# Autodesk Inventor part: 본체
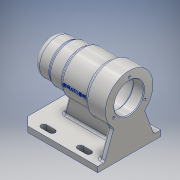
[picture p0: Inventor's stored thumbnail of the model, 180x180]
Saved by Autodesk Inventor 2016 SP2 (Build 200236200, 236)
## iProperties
Created: 2017-09
Part Number: 본체
Material: 알루미늄 6061
Document SubType Name: 모델링
Designer: Administrator
Density: 2.7 g/cm^3
Appearance: 알루미늄 - 평지
Sheet Metal Rule: 기본값_mm
Mass: 696.428 g
Surface Area: 709.296 cm^2
Volume: 257.936 cm^3
Author: Administrator
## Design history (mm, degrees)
sketch "스케치1"
  geometry: L1 (-56, -45)-(56, -45); L2 (56, -45)-(56, 45); L3 (56, 45)-(-56, 45); L4 (-56, 45)-(-56, -45); L5 (-56, -45)-(56, 45); L6 (56, -45)-(-56, 45); 1 further point
  constraints: 12 end point, 2 midpoint, 2 parallel, 1 horizontal, 1 perpendicular
  dimensions: "d0" = 112 distance of L2.end L3.end; "d1" = 90 distance of L1.end L2.end
extrude "돌출1" new body sketch "스케치1" distance "d2" = 8; taper "d3" = 0 deg
sketch "스케치4"
  geometry: L1 (56, 70)-(31, 70); L2 (31, 70)-(31, 95); L3 (31, 95)-(56, 95); L4 (56, 95)-(56, 70); L5 (31, 70)-(11, 70); L6 (11, 70)-(11, 97); L7 (11, 97)-(31, 97); L8 (31, 97)-(31, 70); L9 (11, 70)-(-28, 70); L10 (-28, 70)-(-28, 100); L11 (-28, 100)-(11, 100); L12 (11, 100)-(11, 70); L13 (-28, 70)-(-56, 70); L14 (-56, 70)-(-56, 104); L15 (-56, 104)-(-28, 104); L16 (-28, 104)-(-28, 70); L17 (-56, 0)-(-56, 8) reference; L18 (-56, 0)-(56, 0) reference; 1 further point
  constraints: 32 end point, 8 parallel, 4 horizontal, 4 perpendicular, 1 collinear
  dimensions: "d20" = 112 distance between parallel lines of L14 L4; "d21" = 25 distance of L2.end L3.end; "d22" = 45 distance between parallel lines of L6 L4; "d23" = 84 distance between parallel lines of L10 L4; "d24" = 70 distance between parallel lines of L18 L13; "d25" = 50 diameter of L3 L1; "d26" = 54 diameter of L7 L5; "d27" = 60 diameter of L11 L9; "d28" = 68 diameter of L15 L13
revolve "회전1" sketch "스케치4" stored, may be unused: angle "d29" = 90 deg
fillet "모깎기1" dims "d39" = 9
fillet "모깎기2" dims "d40" = 3
sketch "스케치7" dims "d52" = 0
  geometry: L1 (-56, 8)-(56, 8) reference; L2 (-56, 8)-(34, 8); L3 (34, 8)-(17.387, 70); L4 (17.387, 70)-(-56, 70); L5 (14, 97)-(14, 43) reference; L6 (-56, 70)-(-56, 8); L7 (-56, 0)-(56, 0) reference; L8 (56, 0)-(56, 8) reference; 1 further point
  constraints: 8 end point, 2 perpendicular, 1 point on line
  dimensions: "d41" = 70 distance between parallel lines of L7 L4; "d42" = 22 distance from line of L8 L2.end; "d43" = 105 deg angle of L1 L3
extrude "돌출5" join sketch "스케치7" stored distance "d44" = 8; taper "d45" = 0 deg
sketch "스케치8"
  geometry: L1 (-8, 90)-(-8, 0) reference; L2 (-8, 10)-(-70, 32.566); L3 (-70, 32.566)-(-70, 57.434); L4 (-70, 57.434)-(-8, 80); L5 (-8, 80)-(-8, 10); L6 (0, 0)-(-8, 0) reference; L7 (0, 90)-(-8, 90) reference; L8 (0, 90)-(0, 0) reference; 1 further point
  constraints: 8 end point, 2 point on line, 1 parallel, 1 vertical
  dimensions: "d46" = 10 distance from line of L6 L2.start; "d47" = 10 distance from line of L7 L4.end; "d48" = 110 deg angle of L1 L4; "d49" = 110 deg angle of L1 L2; "d50" = 70 distance between parallel lines of L8 L3
extrude "돌출6" join sketch "스케치8" distance "d51" = 8; taper "d52" = 0 deg
sketch "스케치9"
  geometry: L1 (-32, 34)-(-20, 34); L2 (-32, 30)-(-20, 30); L3 (-20, 38)-(-32, 38); L4 (20, 34)-(32, 34); L5 (20, 30)-(32, 30); L6 (32, 38)-(20, 38); L7 (56, -45)-(56, 45) reference; A1 r 4 centre (-32, 34) between (-32, 38) and (-32, 30); A2 r 4 centre (-20, 34) between (-20, 30) and (-20, 38); A3 r 4 centre (20, 34) between (20, 38) and (20, 30); A4 r 4 centre (32, 34) between (32, 30) and (32, 38); 3 further points
  constraints: 16 end point, 8 point on circle, 8 tangent, 4 centre point, 2 horizontal, 2 midpoint, 2 parallel, 1 horizontal alignment
  dimensions: "d53" = 34 vertical distance of point (0, 0) point (-26, 34); "d54" = 4 radius of A1; "d56" = 12 distance of L1.end L1.start; "d57" = 40 distance of L4.start L1.end; "d58" = 12 distance of L4.start L4.end; "d59" = 24 distance from line of L7 L4.end; "d60" = 4 radius of A3; "d61" = 4 radius of A2 (derived); "d62" = 4 radius of A4 (derived)
extrude "돌출7" cut sketch "스케치9" stored distance "d63" = 8; taper "d64" = 0 deg
chamfer "모따기1" distance "d65" = 12; stored, may be unused: second distance "d66" = 2, angle "d67" = 45 deg
sketch "스케치10"
  geometry: L1 (-56, 43.992)-(-56, 104) reference; L2 (-56, 70)-(-41, 70); L3 (-41, 70)-(-41, 91); L4 (-41, 91)-(-56, 91); L5 (-56, 91)-(-56, 70); L6 (-41, 70)-(13, 70); L7 (13, 70)-(13, 94); L8 (13, 94)-(-41, 94); L9 (-41, 94)-(-41, 70); L10 (13, 86.642)-(13, 70); L11 (-56, 0)-(44, 0) reference; L12 (13, 70)-(25, 70); L13 (25, 70)-(25, 91); L14 (25, 91)-(13, 91); L15 (13, 91)-(13, 70); L16 (25, 70)-(43, 70); L17 (43, 70)-(43, 87.5); L18 (43, 87.5)-(25, 87.5); L19 (25, 87.5)-(25, 70); L20 (43, 70)-(47, 70); L21 (47, 86)-(43, 86); L22 (43, 86)-(43, 70); L23 (47, 70)-(50, 70); L24 (50, 70)-(50, 80.5); L25 (50, 80.5)-(47, 80.5); L26 (47, 80.5)-(47, 70); L27 (47, 86)-(47, 70); L28 (47, 45)-(47, 95) reference; 1 further point
  constraints: 50 end point, 11 parallel, 6 horizontal, 5 perpendicular, 1 collinear, 1 point on line
  dimensions: "d68" = 70 distance between parallel lines of L11 L2; "d69" = 15 distance of L3.end L4.end; "d70" = 54 distance of L7.end L8.end; "d73" = 12 distance of L13.end L14.end; "d74" = 18 distance of L17.end L18.end; "d75" = 4 distance of L21.start L21.end; "d77" = 42 diameter of L4 L2; "d78" = 48 diameter of L8 L6; "d79" = 42 diameter of L14 L12; "d80" = 35 diameter of L18 L16; "d81" = 32 diameter of L21 L20; "d84" = 21 diameter of L25 L23; "d86" = 3 distance between parallel lines of L24 L27; "d105" = 7 distance between parallel lines of L22 L24 (derived)
revolve "회전2" sketch "스케치10" stored, may be unused: angle "d87" = 90 deg
fillet "모깎기3" dims "d88" = 3
fillet "모깎기4" dims "d89" = 0.3
fillet "모깎기5" dims "d90" = 3
chamfer "모따기2" distance "d91" = 1; stored, may be unused: second distance "d92" = 2, angle "d93" = 45 deg
sketch "스케치11" dims "d94" = 52
  geometry: C1 r 24 at (-70, 45) reference; C2 r 27 at (-70, 45) reference; 3 further points
  constraints: 1 coincident, 1 horizontal alignment, 2 other
hole "구멍1" sketch "스케치11" at (-96, 45) diameter "d95" = 3.242; stored, may be unused: countersink angle "d99" = 90 deg, drill point angle "d101" = 118 deg; dims "d96" = 8, "d97" = 4, "d98" = 2, "d100" = 11.8
fillet "모깎기6" dims "d106" = 3
sketch "스케치12"
  geometry: L1 (-176.004, 80.273)-(80.004, 80.273); L2 (80.004, 80.273)-(80.004, 59.727); L3 (80.004, 59.727)-(-176.004, 59.727); L4 (-176.004, 59.727)-(-176.004, 80.273); L5 (-176.004, 70)-(80.004, 70); L6 (-48, 70)-(-48, 59.727); L7 (-100, 0)-(0, 0) reference; L8 (0, 104)-(0, 45.289) reference; 1 further point
  constraints: 4 end point, 4 midpoint, 2 other
  dimensions: "d107" = 70 distance between parallel lines of L7 L5; "d108" = 48 distance between parallel lines of L8 L6
feature "엠보싱1" sketch "스케치12" dims "d20" = 112, "d21" = 25, "d22" = 45, "d23" = 84, "d24" = 70, "d25" = 50, "d26" = 54, "d27" = 60, "d28" = 68, "d109" = 0.5, "d110" = 0
node "솔리드1"
mirror "대칭1"
pattern_circular "원형 패턴1" dims angle "d103" = 360 deg
other parameters: "Thickness" = 0.5, "BendRadius" = 0.5 (= Thickness), "BendReliefWidth" = 0.5 (= Thickness), "BendReliefDepth" = 0.25 (= 0.5 x Thickness), "CornerReliefSize" = 2 (= 4 x Thickness), "SeamGap" = 0.01, "MinimumRemnant" = 1 (= 2 x Thickness), "TransitionRadius" = 0.5 (= BendRadius), "JacobiRadiusSize" = 0.5 (= BendRadius), "GapSize" = 0.5 (= Thickness)
